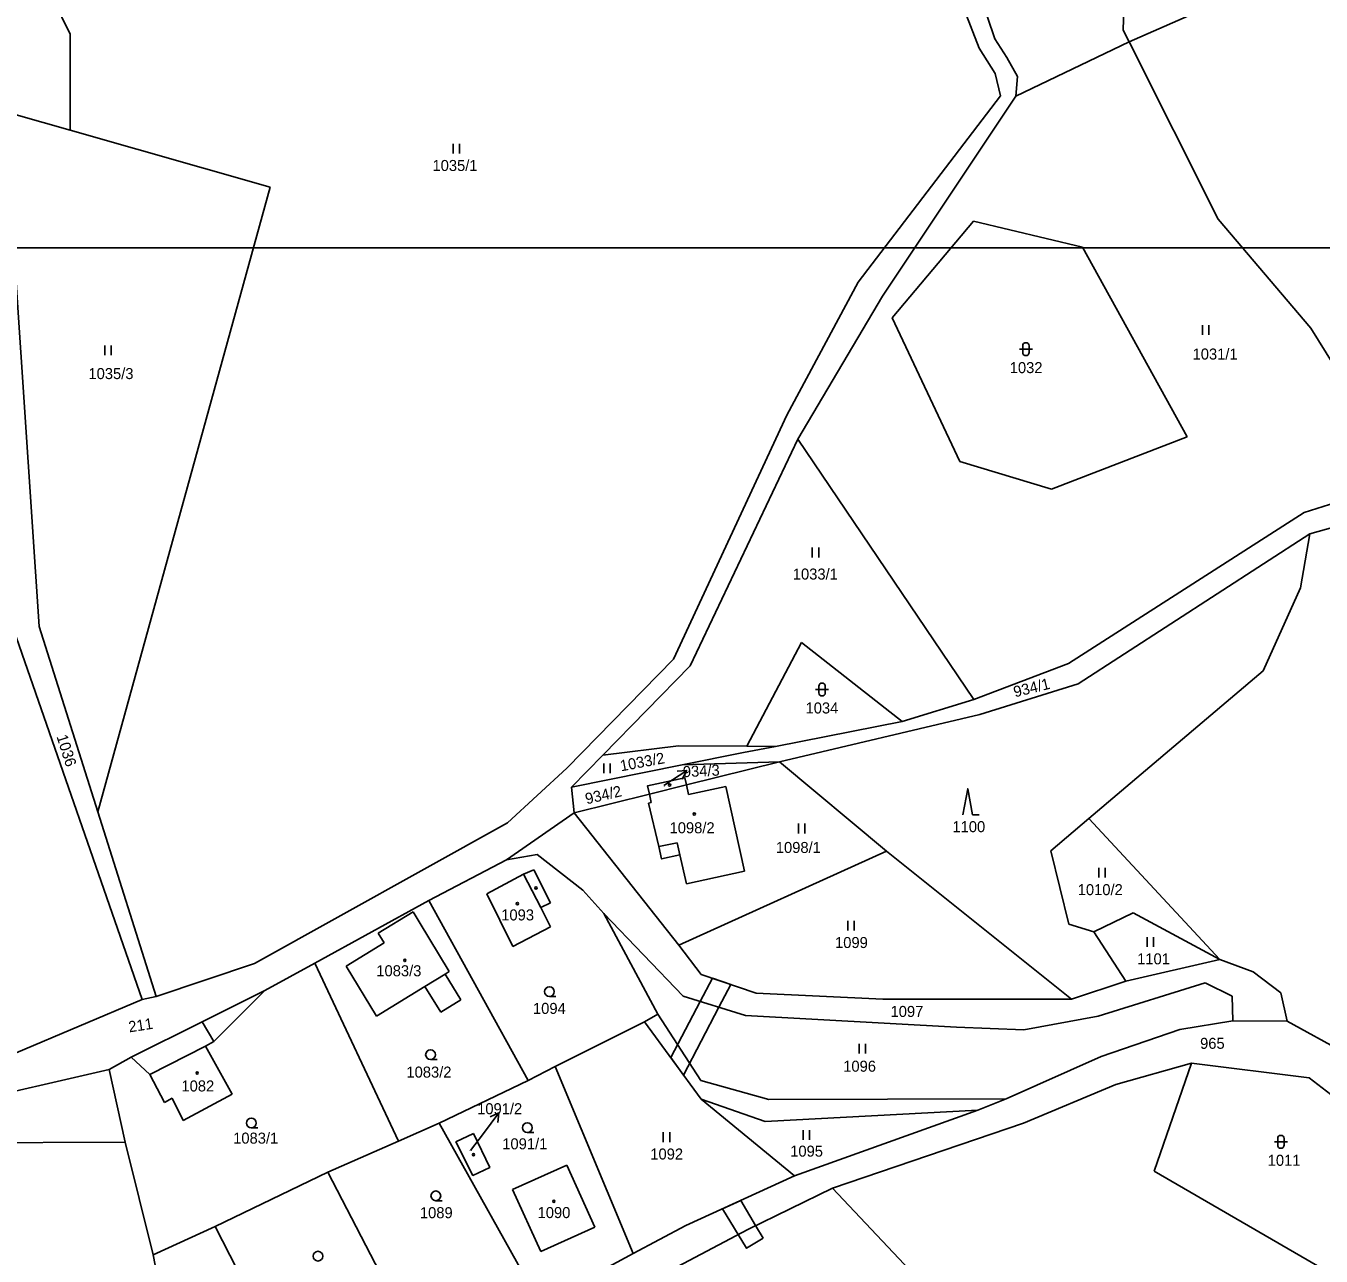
# Model space of a CAD drawing. Extents: x -670359 to -660124, y -978807 to -970072.
# Drawn here: x -669982.9 to -669783.1, y -977655.6 to -977465.8 of the extents above; entities that cross this region are included whole.
import ezdxf

# ---------------------------------------------------------------- set-up
doc = ezdxf.new("R2010")
doc.units = 0
for name, color, linetype in [('Hranice parcel', 7, 'Continuous'), ('ML1000', 7, 'Continuous'), ('Parcelní čísla', 7, 'Continuous'), ('Vnitřní kresba', 7, 'Continuous'), ('Věcná břemena k části', 7, 'Continuous'), ('Značky budov', 7, 'Continuous'), ('Značky kultur', 7, 'Continuous')]:
    doc.layers.add(name, color=color, linetype=linetype)

msp = doc.modelspace()

# ---------------------------------------------------------------- linework, layer by layer
at = {"layer": 'Hranice parcel'}
msp.add_line((-669984.43, -977479.49), (-669976.06, -977481.88), dxfattribs=at)
for points in [[(-669812.71, -977468.21), (-669744.27, -977438.16)], [(-669813.61, -977466.42), (-669812.79, -977439.64)], [(-669835.84, -977469.21), (-669845.07, -977445.27)], [(-669841.15, -977444.93), (-669833.41, -977467.78)], [(-669981.31, -977456.31), (-669976.1, -977467.06), (-669976.06, -977481.88)], [(-669813.61, -977466.42), (-669812.71, -977468.21)], [(-669833.41, -977467.78), (-669831.59, -977470.66)], [(-669830.18, -977476.59), (-669812.71, -977468.21)], [(-669798.98, -977495.58), (-669812.71, -977468.21)], [(-669833.39, -977473.09), (-669835.84, -977469.21)], [(-669831.59, -977470.66), (-669829.92, -977473.59)], [(-669832.56, -977476.56), (-669833.39, -977473.09)], [(-669829.92, -977473.59), (-669830.18, -977476.59)], [(-669854.5, -977505.34), (-669832.56, -977476.56)], [(-669830.18, -977476.59), (-669850.73, -977507.48)], [(-669976.06, -977481.88), (-669945.24, -977490.65)], [(-669945.24, -977490.65), (-669971.83, -977587.05)], [(-669985.41, -977490.75), (-669980.86, -977558.44)], [(-669849.27, -977510.82), (-669836.72, -977495.89)], [(-669836.72, -977495.89), (-669819.9, -977499.94)], [(-669784.65, -977512.44), (-669798.98, -977495.58)], [(-669819.9, -977499.94), (-669803.75, -977529.17)], [(-669865.51, -977525.87), (-669854.5, -977505.34)], [(-669850.73, -977507.48), (-669863.81, -977529.57)], [(-669838.84, -977532.98), (-669849.27, -977510.82)], [(-669770.05, -977535.92), (-669784.65, -977512.44)], [(-669882.98, -977563.53), (-669865.51, -977525.87)], [(-669863.81, -977529.57), (-669880.41, -977564.55)], [(-669836.64, -977569.73), (-669863.81, -977529.57)], [(-669803.75, -977529.17), (-669824.66, -977537.29)], [(-669824.66, -977537.29), (-669838.84, -977532.98)], [(-669785.7, -977540.89), (-669770.05, -977535.92)], [(-669769.39, -977539.84), (-669784.8, -977544.16)], [(-669785.7, -977540.89), (-669822.04, -977564.2)], [(-669784.8, -977544.16), (-669820.58, -977567.31)], [(-669786.27, -977552.48), (-669784.8, -977544.16)], [(-669792.04, -977565.3), (-669786.27, -977552.48)], [(-669980.86, -977558.44), (-669971.83, -977587.05)], [(-669964.98, -977616.04), (-669984.78, -977559.05)], [(-669863.24, -977560.93), (-669871.66, -977576.95)], [(-669847.74, -977573.15), (-669863.24, -977560.93)], [(-669899.44, -977580.33), (-669882.98, -977563.53)], [(-669880.41, -977564.55), (-669893.88, -977578.3)], [(-669822.04, -977564.2), (-669836.64, -977569.73)], [(-669818.93, -977588.12), (-669792.04, -977565.3)], [(-669820.58, -977567.31), (-669835.75, -977572.04)], [(-669836.64, -977569.73), (-669847.74, -977573.15)], [(-669835.75, -977572.04), (-669866.66, -977579.33)], [(-669847.74, -977573.15), (-669867.27, -977576.97)], [(-669898.75, -977583.26), (-669893.88, -977578.3)], [(-669893.88, -977578.3), (-669882.23, -977576.89)], [(-669882.23, -977576.89), (-669871.66, -977576.95)], [(-669872.18, -977577.93), (-669881.64, -977579.83)], [(-669872.18, -977577.93), (-669867.27, -977576.97)], [(-669871.66, -977576.95), (-669867.27, -977576.97)], [(-669908.59, -977588.77), (-669899.44, -977580.33)], [(-669898.75, -977583.26), (-669881.64, -977579.83)], [(-669881.64, -977579.83), (-669866.66, -977579.33)], [(-669881.01, -977582.92), (-669866.66, -977579.33)], [(-669850.11, -977593.14), (-669866.66, -977579.33)], [(-669886.72, -977584.35), (-669887, -977583.04), (-669881.24, -977581.81), (-669881.01, -977582.92)], [(-669898.75, -977583.26), (-669898.3, -977587.24)], [(-669898.3, -977587.24), (-669886.72, -977584.35)], [(-669886.72, -977584.35), (-669881.01, -977582.92)], [(-669886.72, -977584.35), (-669886.45, -977585.64)], [(-669880.69, -977584.4), (-669881.01, -977582.92)], [(-669880.69, -977584.4), (-669874.92, -977583.17)], [(-669874.92, -977583.17), (-669872.03, -977596.22)], [(-669886.84, -977585.72), (-669886.45, -977585.64)], [(-669885.24, -977592.42), (-669886.84, -977585.72)], [(-669962.83, -977615.55), (-669971.83, -977587.05)], [(-669898.3, -977587.24), (-669908.78, -977594.46)], [(-669882.18, -977607.64), (-669898.3, -977587.24)], [(-669824.76, -977593.07), (-669818.93, -977588.12)], [(-669818.93, -977588.12), (-669798.68, -977609.85)], [(-669947.66, -977610.5), (-669908.59, -977588.77)], [(-669885.24, -977592.42), (-669884.82, -977594.34), (-669882, -977593.7)], [(-669908.78, -977594.46), (-669920.75, -977600.73)], [(-669904.05, -977593.68), (-669908.78, -977594.46)], [(-669896.98, -977599.14), (-669904.05, -977593.68)], [(-669850.11, -977593.14), (-669882.18, -977607.64)], [(-669882, -977593.7), (-669880.97, -977598.18)], [(-669821.6, -977615.98), (-669850.11, -977593.14)], [(-669821.98, -977604.4), (-669824.76, -977593.07)], [(-669906.15, -977596.67), (-669904.55, -977596.02)], [(-669904.55, -977596.02), (-669901.97, -977601.12)], [(-669872.03, -977596.22), (-669880.97, -977598.18)], [(-669911.81, -977599.74), (-669906.15, -977596.67)], [(-669907.77, -977607.87), (-669911.81, -977599.74)], [(-669893.72, -977602.75), (-669896.98, -977599.14)], [(-669920.75, -977600.73), (-669938.33, -977610.41)], [(-669928.54, -977605.79), (-669923.14, -977602.52)], [(-669923.14, -977602.52), (-669922.22, -977604.03)], [(-669920.75, -977600.73), (-669905.42, -977628.55)], [(-669901.97, -977601.12), (-669903.48, -977601.85)], [(-669903.48, -977601.85), (-669901.95, -977604.8)], [(-669922.22, -977604.03), (-669917.6, -977611.72)], [(-669881.5, -977615.54), (-669893.72, -977602.75)], [(-669885.4, -977618.28), (-669893.72, -977602.75)], [(-669818.13, -977605.58), (-669821.98, -977604.4)], [(-669812.07, -977602.66), (-669818.13, -977605.58)], [(-669798.68, -977609.85), (-669812.07, -977602.66)], [(-669927.62, -977607.3), (-669928.54, -977605.79)], [(-669901.95, -977604.8), (-669907.77, -977607.87)], [(-669818.13, -977605.58), (-669813.21, -977613.22)], [(-669933.52, -977610.88), (-669927.62, -977607.3)], [(-669878.72, -977612.17), (-669882.18, -977607.64)], [(-669962.83, -977615.55), (-669947.66, -977610.5)], [(-669946.04, -977614.65), (-669938.33, -977610.41)], [(-669925.44, -977637.89), (-669938.33, -977610.41)], [(-669798.68, -977609.85), (-669813.21, -977613.22)], [(-669793.55, -977611.74), (-669798.68, -977609.85)], [(-669928.84, -977618.61), (-669933.52, -977610.88)], [(-669917.6, -977611.72), (-669918.23, -977612.1)], [(-669915.8, -977616.07), (-669918.23, -977612.1)], [(-669870.22, -977615.08), (-669878.72, -977612.17)], [(-669789.29, -977614.99), (-669793.55, -977611.74)], [(-669921.34, -977614.01), (-669928.84, -977618.61)], [(-669921.34, -977614.01), (-669918.91, -977617.98)], [(-669813.21, -977613.22), (-669821.6, -977615.98)], [(-669800.98, -977613.46), (-669817.5, -977618.6)], [(-669796.81, -977615.52), (-669800.98, -977613.46)], [(-669964.98, -977616.04), (-669994.19, -977628.36)], [(-669962.83, -977615.55), (-669964.98, -977616.04)], [(-669955.69, -977619.5), (-669946.04, -977614.65)], [(-669918.91, -977617.98), (-669915.8, -977616.07)], [(-669871.88, -977618.52), (-669881.5, -977615.54)], [(-669850.71, -977616), (-669870.22, -977615.08)], [(-669821.6, -977615.98), (-669850.71, -977616)], [(-669796.71, -977619.35), (-669796.81, -977615.52)], [(-669788.31, -977619.38), (-669789.29, -977614.99)], [(-669887.48, -977619.5), (-669885.4, -977618.28)], [(-669839.33, -977620.33), (-669871.88, -977618.52)], [(-669817.5, -977618.6), (-669828.93, -977620.74)], [(-669966.69, -977624.92), (-669955.69, -977619.5)], [(-669955.69, -977619.5), (-669953.91, -977622.53)], [(-669901.27, -977626.37), (-669887.48, -977619.5)], [(-669878.74, -977631.4), (-669887.48, -977619.5)], [(-669828.93, -977620.74), (-669839.33, -977620.33)], [(-669796.71, -977619.35), (-669804.86, -977620.68)], [(-669788.31, -977619.38), (-669796.71, -977619.35)], [(-669770.74, -977629.03), (-669788.31, -977619.38)], [(-669953.91, -977622.53), (-669955.19, -977623.25)], [(-669804.86, -977620.68), (-669816.99, -977624.83)], [(-669955.19, -977623.25), (-669951.07, -977630.66)], [(-669970.04, -977626.86), (-669966.69, -977624.92)], [(-669963.8, -977627.62), (-669966.69, -977624.92)], [(-669905.42, -977628.55), (-669901.27, -977626.37)], [(-669889.2, -977655.23), (-669901.27, -977626.37)], [(-669816.99, -977624.83), (-669831.67, -977631.39)], [(-669814.73, -977629.13), (-669803.07, -977625.86)], [(-669808.82, -977642.52), (-669803.07, -977625.86)], [(-669803.07, -977625.86), (-669784.93, -977628.12)], [(-669993.29, -977632.19), (-669970.04, -977626.86)], [(-669970.04, -977626.86), (-669967.58, -977638.03)], [(-669961.54, -977631.92), (-669963.8, -977627.62)], [(-669905.42, -977628.55), (-669919.14, -977635.11)], [(-669772.22, -977637.91), (-669784.93, -977628.12)], [(-669829.01, -977635.13), (-669814.73, -977629.13)], [(-669960.34, -977631.28), (-669961.54, -977631.92)], [(-669958.65, -977634.7), (-669960.34, -977631.28)], [(-669951.07, -977630.66), (-669958.65, -977634.7)], [(-669868.84, -977634.89), (-669878.74, -977631.4)], [(-669864.32, -977643.24), (-669878.74, -977631.4)], [(-669831.67, -977631.39), (-669836.06, -977633.09)], [(-669836.06, -977633.09), (-669868.84, -977634.89)], [(-669836.06, -977633.09), (-669864.32, -977643.24)], [(-669919.14, -977635.11), (-669925.44, -977637.89)], [(-669903.55, -977663.02), (-669919.14, -977635.11)], [(-669858.47, -977645.13), (-669829.01, -977635.13)], [(-669967.58, -977638.03), (-669963.25, -977655.43)], [(-669936.3, -977642.69), (-669925.44, -977637.89)], [(-669913.84, -977636.7), (-669911.34, -977641.95), (-669913.94, -977643.19), (-669916.57, -977638.01), (-669913.84, -977636.7)], [(-669907.81, -977645.35), (-669899.43, -977641.62)], [(-669899.43, -977641.62), (-669895.14, -977651.19)], [(-669773.6, -977662.93), (-669808.82, -977642.52)], [(-669936.3, -977642.69), (-669953.69, -977651.05)], [(-669920.94, -977672.36), (-669936.3, -977642.69)], [(-669864.32, -977643.24), (-669881.07, -977650.94)], [(-669903.44, -977654.91), (-669907.81, -977645.35)], [(-669858.47, -977645.13), (-669871.55, -977651.52)], [(-669858.47, -977645.13), (-669843.94, -977660.55)], [(-669953.69, -977651.05), (-669963.25, -977655.43)], [(-669943.49, -977671.09), (-669953.69, -977651.05)], [(-669871.55, -977651.52), (-669918.75, -977676.5)], [(-669895.14, -977651.19), (-669903.44, -977654.91)], [(-669881.07, -977650.94), (-669889.2, -977655.23)], [(-669963.25, -977655.43), (-669957.62, -977684.64)], [(-669889.2, -977655.23), (-669903.55, -977663.02)]]:
    msp.add_lwpolyline(points, dxfattribs=at)
at = {"layer": 'ML1000'}
msp.add_lwpolyline([(-669375, -977000), (-669375, -977500), (-670000, -977500), (-670000, -977000)], close=True, dxfattribs=at)
at = {"layer": 'Parcelní čísla'}
for p, q in [((-669882.45, -977580.78), (-669880.96, -977580.7)), ((-669884.46, -977582.98), (-669884.31, -977582.88)), ((-669911.3, -977634.12), (-669909.92, -977633.53)), ((-669914.29, -977639.35), (-669912.32, -977636.73))]:
    msp.add_line(p, q, dxfattribs=at)
for points in [[(-669884.31, -977582.88), (-669880.96, -977580.7), (-669881.64, -977582.04)], [(-669912.32, -977636.73), (-669909.92, -977633.53), (-669910.1, -977635.02)]]:
    msp.add_lwpolyline(points, dxfattribs=at)
at = {"layer": 'Vnitřní kresba'}
for points in [[(-669885.24, -977592.42), (-669882.42, -977591.84)], [(-669882.42, -977591.84), (-669882, -977593.7)], [(-669903.48, -977601.85), (-669906.15, -977596.67)], [(-669918.23, -977612.1), (-669921.34, -977614.01)], [(-669953.91, -977622.53), (-669946.04, -977614.65)], [(-669885.4, -977618.28), (-669878.79, -977628.55)], [(-669963.8, -977627.62), (-669955.19, -977623.25)], [(-669878.79, -977628.55), (-669868.3, -977631.45)], [(-669868.3, -977631.45), (-669831.67, -977631.39)], [(-669993.01, -977638.18), (-669967.58, -977638.03)]]:
    msp.add_lwpolyline(points, dxfattribs=at)
at = {"layer": 'Věcná břemena k části'}
for points in [[(-669883.43, -977625.01), (-669878.88, -977616.35), (-669876.99, -977612.76), (-669874.16, -977613.73), (-669876, -977617.24), (-669881.46, -977627.69), (-669883.43, -977625.01)], [(-669869.15, -977652.89), (-669871.72, -977654.44), (-669875.42, -977648.34), (-669872.61, -977647.05), (-669870.32, -977650.92), (-669869.15, -977652.89)]]:
    msp.add_lwpolyline(points, dxfattribs=at)
at = {"layer": 'Značky budov'}
for centre in [(-669879.79, -977587.41), (-669907.07, -977601.23), (-669924.44, -977610.01), (-669956.48, -977627.39), (-669913.85, -977640), (-669901.46, -977647.17)]:
    msp.add_circle(centre, 0.175, dxfattribs=at)
at = {"layer": 'Značky kultur'}
for p, q in [((-669917, -977483.96), (-669917, -977485.46)), ((-669916, -977485.46), (-669916, -977483.96)), ((-669801.39, -977511.96), (-669801.39, -977513.46)), ((-669800.39, -977513.46), (-669800.39, -977511.96)), ((-669970.73, -977515.1), (-669970.73, -977516.6)), ((-669969.73, -977516.6), (-669969.73, -977515.1)), ((-669829.62, -977515.66), (-669827.62, -977515.66)), ((-669829.12, -977515.16), (-669829.12, -977516.16)), ((-669828.12, -977515.16), (-669828.12, -977516.16)), ((-669861.59, -977546.29), (-669861.59, -977547.79)), ((-669860.59, -977547.79), (-669860.59, -977546.29)), ((-669861.08, -977568.19), (-669859.08, -977568.19)), ((-669860.58, -977567.69), (-669860.58, -977568.69)), ((-669859.58, -977567.69), (-669859.58, -977568.69)), ((-669893.76, -977579.62), (-669893.76, -977581.12)), ((-669892.76, -977581.12), (-669892.76, -977579.62)), ((-669863.73, -977588.89), (-669863.73, -977590.39)), ((-669862.73, -977590.39), (-669862.73, -977588.89)), ((-669817.38, -977595.69), (-669817.38, -977597.19)), ((-669816.38, -977597.19), (-669816.38, -977595.69)), ((-669856.11, -977603.89), (-669856.11, -977605.39)), ((-669855.11, -977605.39), (-669855.11, -977603.89)), ((-669809.92, -977606.41), (-669809.92, -977607.91)), ((-669808.92, -977607.91), (-669808.92, -977606.41)), ((-669902.13, -977615.56), (-669901.13, -977615.56)), ((-669854.37, -977622.86), (-669854.37, -977624.36)), ((-669853.37, -977624.36), (-669853.37, -977622.86)), ((-669920.48, -977625.3), (-669919.48, -977625.3)), ((-669948.12, -977635.85), (-669947.12, -977635.85)), ((-669905.55, -977636.57), (-669904.55, -977636.57)), ((-669884.57, -977636.53), (-669884.57, -977638.03)), ((-669883.57, -977638.03), (-669883.57, -977636.53)), ((-669862.99, -977636.21), (-669862.99, -977637.71)), ((-669861.99, -977637.71), (-669861.99, -977636.21)), ((-669790.28, -977638), (-669788.28, -977638)), ((-669789.78, -977637.5), (-669789.78, -977638.5)), ((-669788.78, -977637.5), (-669788.78, -977638.5)), ((-669919.66, -977647.09), (-669918.66, -977647.09))]:
    msp.add_line(p, q, dxfattribs=at)
msp.add_lwpolyline([(-669838.35, -977587.51), (-669837.6, -977583.51), (-669836.85, -977587.51), (-669835.85, -977587.51)], dxfattribs=at)
for centre, radius in [((-669883.6, -977582.94), 0.175), ((-669879.79, -977587.41), 0.175), ((-669904.22, -977598.82), 0.175), ((-669907.07, -977601.23), 0.175), ((-669924.44, -977610.01), 0.175), ((-669902.13, -977614.81), 0.75), ((-669920.48, -977624.55), 0.75), ((-669956.48, -977627.39), 0.175), ((-669948.12, -977635.1), 0.75), ((-669905.55, -977635.82), 0.75), ((-669913.85, -977640), 0.175), ((-669919.66, -977646.34), 0.75), ((-669901.46, -977647.17), 0.175), ((-669937.85, -977655.65), 0.75)]:
    msp.add_circle(centre, radius, dxfattribs=at)
for centre, start, end in [((-669828.62, -977515.16), 0, 180), ((-669828.62, -977516.16), 180, 0), ((-669860.08, -977567.69), 0, 180), ((-669860.08, -977568.69), 180, 0), ((-669789.28, -977637.5), 0, 180), ((-669789.28, -977638.5), 180, 0)]:
    msp.add_arc(centre, 0.5, start, end, dxfattribs=at)

# ---------------------------------------------------------------- texts
at = {"layer": 'Parcelní čísla'}
for s, height, p in [('1035/1', 1.7, (-669920.18, -977488.16)), ('1031/1', 1.7, (-669802.91, -977517.26)), ('1035/3', 1.7, (-669973.26, -977520.28)), ('1032', 1.7, (-669831.12, -977519.36)), ('1033/1', 1.7, (-669864.59, -977551.22)), ('1034', 1.7, (-669862.62, -977571.89)), ('934/3', 0.1, (-669884.64, -977583.16)), ('1098/2', 1.7, (-669883.6, -977590.38)), ('1100', 1.7, (-669839.96, -977590.21)), ('1098/1', 1.7, (-669867.21, -977593.42)), ('1010/2', 1.7, (-669820.63, -977599.93)), ('1093', 1.7, (-669909.57, -977603.83)), ('1099', 1.7, (-669858.07, -977608.09)), ('1101', 1.7, (-669811.46, -977610.61)), ('1083/3', 1.7, (-669928.84, -977612.45)), ('1094', 1.7, (-669904.67, -977618.26)), ('1097', 1.7, (-669849.51, -977618.73)), ('965', 1.7, (-669801.75, -977623.65)), ('1083/2', 1.7, (-669924.2, -977628.09)), ('1096', 1.7, (-669856.81, -977627.18)), ('1082', 1.7, (-669958.91, -977630.23)), ('1091/2', 1.7, (-669913.29, -977633.74)), ('1083/1', 1.7, (-669950.93, -977638.28)), ('1091/1', 1.7, (-669909.41, -977639.16)), ('1095', 1.7, (-669864.99, -977640.29)), ('1091/2', 0.1, (-669914.52, -977639.35)), ('1092', 1.7, (-669886.57, -977640.73)), ('1011', 1.7, (-669791.32, -977641.7)), ('1089', 1.7, (-669922.12, -977649.79)), ('1090', 1.7, (-669903.96, -977649.77))]:
    msp.add_text(s, height=height, dxfattribs=at).set_placement(p)
for s, rotation, p in [('934/1', 13.7995, (-669830.31, -977569.41)), ('1036', 287.6125, (-669978.2, -977575.44)), ('1033/2', 10.6105, (-669891.08, -977580.83)), ('934/3', 2.6693, (-669881.51, -977581.73)), ('934/2', 13.0634, (-669896.4, -977585.92)), ('211', 8.8394, (-669966.95, -977621.12))]:
    msp.add_text(s, height=1.7, rotation=rotation, dxfattribs=at).set_placement(p)

doc.saveas('drawing.dxf')
